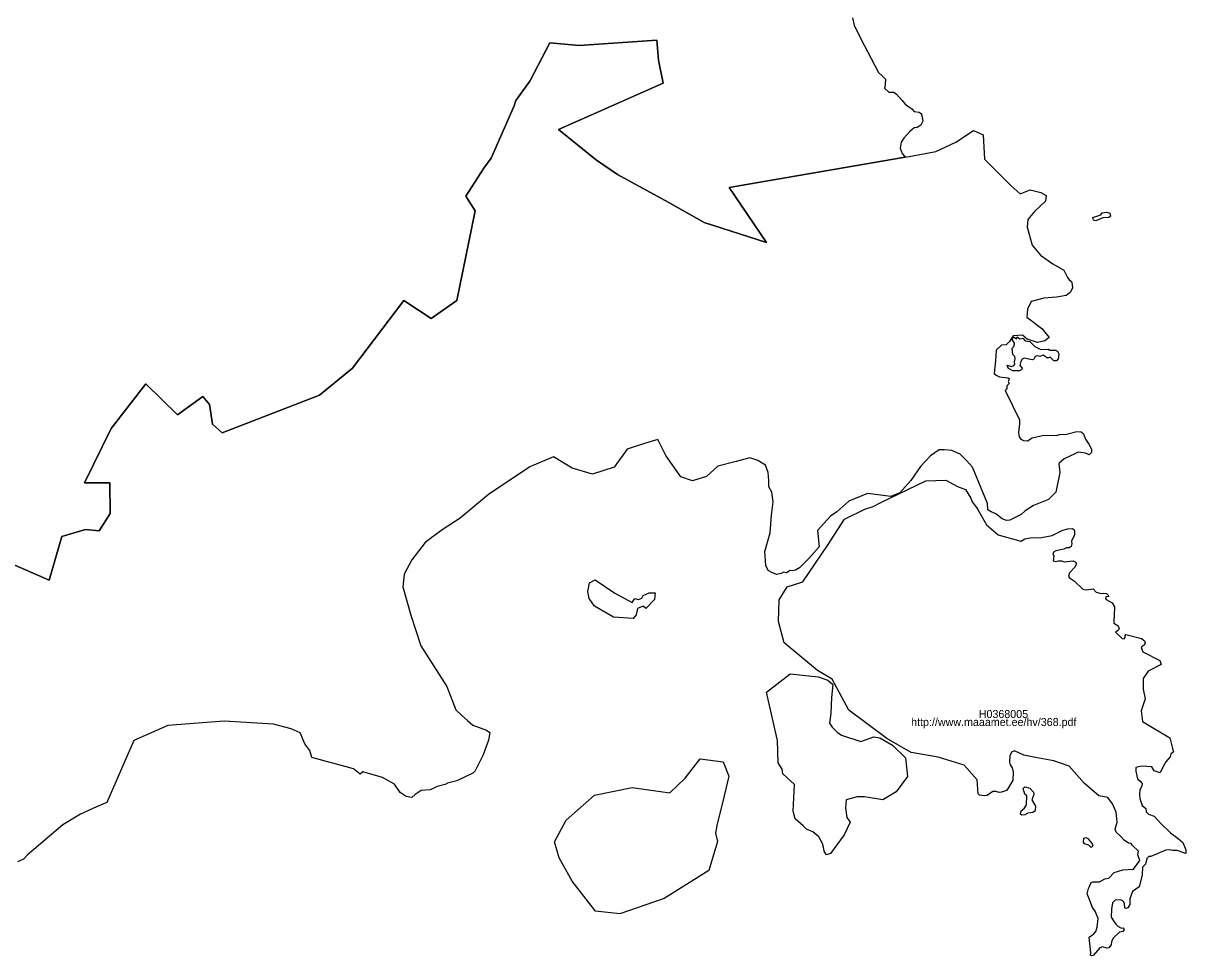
# Model space of a CAD drawing. Extents: x 369010 to 739155, y 6377141 to 6634081.
# Drawn here: x 432069 to 435701, y 6515722 to 6518635 of the extents above; entities that cross this region are included whole.
import ezdxf

# ---------------------------------------------------------------- set-up
doc = ezdxf.new("R2010")
doc.units = 0
for name, color, linetype in [('H_LINK', 7, 'Continuous'), ('H_PIIR', 7, 'Continuous'), ('H_TUNNUS', 7, 'Continuous')]:
    doc.layers.add(name, color=color, linetype=linetype)

msp = doc.modelspace()

# ---------------------------------------------------------------- linework, layer by layer
at = {"layer": 'H_PIIR'}
for points in [[(434660.1, 6518652.0146), (434664.5801, 6518629.5846), (434687.0001, 6518584.7346), (434706.42, 6518547.3647), (434740.79, 6518481.5847), (434752.7399, 6518471.1146), (434763.2001, 6518460.6546), (434761.71, 6518442.7146), (434760.2099, 6518432.2446), (434773.6601, 6518420.2846), (434789.35, 6518420.2846), (434797.1799, 6518413.6347), (434815.29, 6518394.4047), (434823.93, 6518382.9847), (434838.6599, 6518372.4546), (434845.1101, 6518367.6546), (434852.91, 6518360.1246), (434868.51, 6518358.1747), (434875.48, 6518352.0446), (434879.0999, 6518329.4746), (434873.2499, 6518316.9346), (434862.3799, 6518309.6847), (434852.77, 6518308.2846), (434837.45, 6518296.3047), (434820.1699, 6518275.9546), (434811.5299, 6518263.6946), (434809.03, 6518244.7446), (434814.75, 6518228.9347), (434822.22, 6518219.9646), (434823.8759, 6518217.4807), (434818.28, 6518216.51), (434274.3, 6518122.15), (434390.87, 6517950.0801), (434196.5901, 6518012.52), (434084.19, 6518076.3599), (433925.9901, 6518162.3899), (433859.38, 6518208.19), (433741.4201, 6518303.94), (434068.05, 6518448.41), (434053.77, 6518519.84), (434048.06, 6518582.7), (433805.3299, 6518565.56), (433713.95, 6518574.13), (433651.12, 6518454.12), (433608.29, 6518394.12), (433602.58, 6518376.9799), (433531.1899, 6518214.11), (433508.3401, 6518182.6801), (433451.82, 6518095.3999), (433480.37, 6518049.68), (433423.26, 6517769.66), (433343.3001, 6517712.52), (433257.63, 6517769.66), (433097.72, 6517558.2199), (432993.95, 6517473.18), (432689.82, 6517356.03), (432660.27, 6517383.29), (432650.2801, 6517444.7301), (432630.29, 6517469.01), (432550.3299, 6517411.87), (432451.8101, 6517509.01), (432343.3201, 6517369.21), (432260.51, 6517199.2), (432339.04, 6517199.4601), (432340.4701, 6517103.7401), (432306.2, 6517049.4501), (432263.37, 6517053.73), (432189.12, 6517032.3), (432149.14, 6516895.15), (431967.8001, 6516974.8599)], [(431967.8001, 6516974.8599), (432149.14, 6516895.15), (432189.12, 6517032.3), (432263.37, 6517053.73), (432306.2, 6517049.4501), (432340.4701, 6517103.7401), (432339.04, 6517199.4601), (432260.51, 6517199.2), (432343.3201, 6517369.21), (432451.8101, 6517509.01), (432550.3299, 6517411.87), (432630.29, 6517469.01), (432650.2801, 6517444.7301), (432660.27, 6517383.29), (432689.82, 6517356.03), (432993.95, 6517473.18), (433097.72, 6517558.2199), (433257.63, 6517769.66), (433343.3001, 6517712.52), (433423.26, 6517769.66), (433480.37, 6518049.68), (433451.82, 6518095.3999), (433508.3401, 6518182.6801), (433531.1899, 6518214.11), (433602.58, 6518376.9799), (433608.29, 6518394.12), (433651.12, 6518454.12), (433713.95, 6518574.13), (433805.3299, 6518565.56), (434048.06, 6518582.7), (434053.77, 6518519.84), (434068.05, 6518448.41), (433741.4201, 6518303.94), (433859.38, 6518208.19), (433925.9901, 6518162.3899), (434084.19, 6518076.3599), (434196.5901, 6518012.52), (434390.87, 6517950.0801), (434274.3, 6518122.15), (434818.28, 6518216.51), (434823.8759, 6518217.4807), (434836.7915, 6518219.0082), (434920.4, 6518234.3541), (434982.3126, 6518263.9875), (435038.4044, 6518300.2355), (435067.7732, 6518287.0063), (435071.8742, 6518211.203), (435155.2182, 6518127.8591), (435183.9255, 6518102.5913), (435214.4849, 6518115.2913), (435247.8225, 6518106.1632), (435265.285, 6518097.4319), (435262.5069, 6518079.1756), (435228.3756, 6518047.0287), (435207.3412, 6518022.8193), (435205.7537, 6517998.6099), (435221.6287, 6517942.2535), (435247.4256, 6517910.9003), (435285.9226, 6517883.9127), (435320.0539, 6517863.6721), (435331.4163, 6517841.3816), (435336.7299, 6517833.9601), (435343.9194, 6517828.747), (435346.2345, 6517818.8251), (435346.8959, 6517807.5803), (435339.6199, 6517794.3511), (435327.7136, 6517784.7599), (435296.9557, 6517779.1375), (435257.5989, 6517776.161), (435217.9113, 6517765.9083), (435206.3358, 6517741.7651), (435205.0128, 6517717.2911), (435251.6457, 6517681.5722), (435274.1354, 6517654.1217), (435261.2369, 6517643.2076), (435237.7551, 6517637.9159), (435205.3436, 6517648.4993), (435191.1222, 6517660.7363), (435161.6872, 6517659.0826), (435150.4424, 6517640.8373), (435139.7037, 6517630.8062), (435125.7816, 6517629.4936), (435108.8936, 6517613.7185), (435106.87, 6517580.68), (435102.73, 6517541.0146), (435109.13, 6517535.4447), (435119.1701, 6517530.7047), (435145.36, 6517527.3647), (435150.65, 6517524.2946), (435146.05, 6517516.2146), (435149.1199, 6517509.8046), (435141.87, 6517502.5547), (435141.5899, 6517493.9147), (435136.86, 6517487.7846), (435181.86, 6517396.0946), (435181.86, 6517382.7246), (435179.0699, 6517367.3947), (435178.5199, 6517355.6846), (435180.47, 6517342.8646), (435186.32, 6517336.4547), (435193.71, 6517331.4546), (435206.2499, 6517331.1747), (435221.01, 6517339.8147), (435257.5199, 6517348.4447), (435295.8301, 6517347.3247), (435307.8199, 6517350.9446), (435328.44, 6517351.2247), (435360.76, 6517360.1446), (435373.85, 6517359.0346), (435381.38, 6517352.6246), (435387.5101, 6517336.1746), (435398.1, 6517320.8547), (435406.73, 6517304.4046), (435407.0099, 6517294.0947), (435399.77, 6517286.8546), (435387.79, 6517292.7046), (435365.0346, 6517295.033), (435354.7445, 6517290.1781), (435321.07, 6517274.29), (435304.0995, 6517259.8366), (435307.2745, 6517232.3199), (435295.03, 6517169.89), (435272.52, 6517147.82), (435225.2707, 6517128.9103), (435199.26, 6517112.06), (435186.4401, 6517100.9101), (435168.0501, 6517090.88), (435150.92, 6517083.0801), (435140.61, 6517081.9701), (435127.23, 6517087.5401), (435107.73, 6517102.5901), (435092.68, 6517109.0001), (435082.93, 6517115.69), (435081.5301, 6517135.4701), (435034.434, 6517248.3796), (435016.11, 6517269.22), (434995.9187, 6517289.1806), (434969.94, 6517300.18), (434946.15, 6517302.16), (434930.5071, 6517302.17), (434904.0487, 6517284.1783), (434872.2986, 6517250.3116), (434841.6069, 6517206.9198), (434807.7402, 6517168.8197), (434779.1651, 6517157.178), (434707.1983, 6517166.7031), (434647.9315, 6517142.3614), (434611.2013, 6517108.6284), (434590.7628, 6517095.8242), (434550.0024, 6517050.6786), (434555.2941, 6516999.8785), (434523.544, 6516962.8368), (434494.5382, 6516934.4594), (434481.3681, 6516927.2093), (434473.4683, 6516924.5794), (434464.2583, 6516925.2394), (434458.9883, 6516921.9393), (434453.0582, 6516917.9893), (434444.5081, 6516920.6194), (434436.6082, 6516916.6693), (434422.7782, 6516912.7193), (434407.6383, 6516919.3094), (434396.4482, 6516925.2394), (434388.5481, 6516941.7093), (434385.9604, 6516985.0618), (434402.8938, 6517043.2703), (434407.1271, 6517098.3037), (434412, 6517140), (434408.01, 6517170.1747), (434398.79, 6517186.6446), (434398.13, 6517206.4147), (434396.1599, 6517232.1046), (434388, 6517255), (434364.2976, 6517269.3616), (434338.8976, 6517277.8283), (434296.5641, 6517266.1866), (434239.414, 6517251.3699), (434203.4306, 6517219.6198), (434160.0389, 6517205.8615), (434122.9971, 6517218.5615), (434076.4304, 6517285.2366), (434051.0303, 6517334.9784), (434009.7552, 6517322.2784), (433955.7801, 6517304.2867), (433915.5634, 6517248.1949), (433847.8299, 6517227.0282), (433784.3298, 6517245.0199), (433725.063, 6517281.0033), (433652.0379, 6517249.2532), (433522.9209, 6517163.5281), (433434.0208, 6517089.4446), (433377.929, 6517052.4028), (433325.0064, 6517013.2475), (433282.6788, 6516959.2693), (433258.3702, 6516914.3105), (433255.1621, 6516874.6025), (433279.5038, 6516785.9669), (433310.4601, 6516689.9229), (433392.2165, 6516563.7164), (433420.2293, 6516489.9637), (433438.9312, 6516472.6725), (433456.7419, 6516457.4199), (433473.0138, 6516442.7355), (433516.2733, 6516427.2573), (433526.9889, 6516419.3198), (433522.2264, 6516395.1104), (433505.9201, 6516349.6947), (433481.0899, 6516299.9947), (433473.25, 6516292.1446), (433423.8012, 6516268.1101), (433393.8312, 6516261.06), (433387.2713, 6516256.6701), (433361.9753, 6516250.388), (433351.5153, 6516245.148), (433340.0604, 6516240.3288), (433312.2249, 6516238.4615), (433293.5499, 6516226.1047), (433283.0999, 6516216.9447), (433264.8001, 6516219.5646), (433246.8917, 6516232.358), (433228.6016, 6516258.5181), (433191.0997, 6516278.7993), (433130.1899, 6516296.7247), (433121.0399, 6516288.8746), (433100.13, 6516305.8847), (432970.75, 6516341.1946), (432964.2201, 6516363.4247), (432948.5299, 6516384.3547), (432934.1601, 6516418.3547), (432905.41, 6516431.4346), (432850.3157, 6516445.787), (432696.3279, 6516455.312), (432520.115, 6516441.0245), (432414.0351, 6516394.9869), (432329.6146, 6516201.3115), (432297.8646, 6516187.024), (432247.5936, 6516164.7989), (432192.5602, 6516130.9322), (432081.0835, 6516036.6954), (432069.3234, 6516023.6155), (432051.0235, 6516015.7655)]]:
    msp.add_lwpolyline(points, dxfattribs=at)
for points in [[(435442.0215, 6518027.7548), (435420.5061, 6518018.6522), (435413.2238, 6518019.9761), (435410.4103, 6518028.0859), (435435.5669, 6518036.6921), (435440.0354, 6518042.8156), (435454.4344, 6518045.4638), (435464.0336, 6518042.3192), (435465.6886, 6518033.051), (435461.2199, 6518028.4168)], [(435173.9051, 6517656.0329), (435182.3457, 6517649.9093), (435192.1105, 6517652.0609), (435199.0616, 6517643.1235), (435214.1226, 6517641.1376), (435229.1834, 6517625.5802), (435248.0509, 6517616.643), (435271.5523, 6517617.4705), (435276.021, 6517614.1603), (435294.723, 6517613.8294), (435301.5087, 6517609.6918), (435304.4876, 6517601.0856), (435302.3362, 6517587.1832), (435297.04, 6517581.0595), (435288.5993, 6517581.0595), (435277.0139, 6517592.4794), (435269.0698, 6517589.0038), (435255.9951, 6517598.2719), (435245.2372, 6517593.8034), (435236.7965, 6517596.6169), (435230.673, 6517594.631), (435226.2043, 6517586.0247), (435221.2392, 6517583.7077), (435196.0826, 6517588.8382), (435190.4555, 6517585.6936), (435185.3248, 6517579.0735), (435182.3457, 6517565.6677), (435190.4555, 6517557.889), (435189.2969, 6517553.4203), (435182.0148, 6517549.1173), (435160.3336, 6517549.7794), (435146.4314, 6517557.889), (435143.6178, 6517567.6537), (435156.1961, 6517563.3506), (435163.6439, 6517565.9986), (435166.9539, 6517570.6328), (435165.6298, 6517577.9149), (435168.6089, 6517587.1832), (435167.2848, 6517594.631), (435160.8302, 6517600.7545), (435159.1752, 6517619.953), (435164.9678, 6517626.9042), (435166.4573, 6517636.1723), (435160.0027, 6517646.7647), (435161.1612, 6517652.8884), (435164.9678, 6517654.8743), (435172.581, 6517649.5782)], [(435108.01, 6516235.6246), (435098.5401, 6516235.6246), (435080.15, 6516223.0845), (435071.51, 6516221.1346), (435056.74, 6516223.6445), (435052.2799, 6516228.3845), (435049.0332, 6516272.04), (435008.9297, 6516317.2456), (434927.5702, 6516342.381), (434842.8801, 6516357.4246), (434767.497, 6516401.2509), (434648.8311, 6516488.8943), (434596.4435, 6516585.732), (434550.4059, 6516612.7196), (434446.0276, 6516699.5692), (434428.1682, 6516766.3767), (434430.1525, 6516834.507), (434455.1557, 6516874.6576), (434504.3683, 6516890.5326), (434582.156, 6517003.2454), (434634.9964, 6517086.327), (434698.4364, 6517117.397), (434724.151, 6517125.5421), (434748.4396, 6517138.5277), (434888.5441, 6517205.5859), (434951.3828, 6517207.5702), (434987.78, 6517188.46), (435012.8985, 6517179.1275), (435029.7345, 6517151.3233), (435033.6345, 6517140.4533), (435047.2944, 6517122.9034), (435052.5846, 6517113.7034), (435078.383, 6517068.0023), (435115.4247, 6517036.9137), (435186.32, 6517017.6546), (435198.58, 6517024.8947), (435215.0201, 6517027.9646), (435250.6899, 6517028.2447), (435283.43, 6517035.4846), (435317.1401, 6517051.3647), (435332.7501, 6517055.8247), (435347.24, 6517056.3847), (435352.2499, 6517052.4847), (435353.9299, 6517048.0246), (435353.3699, 6517036.8747), (435343.6201, 6517017.3647), (435345.01, 6517009.0046), (435343.34, 6517000.3646), (435337.2099, 6516996.1846), (435328.29, 6516996.1846), (435319.9299, 6516992.5647), (435294.85, 6516987.5446), (435287.89, 6516983.0846), (435285.9401, 6516976.1246), (435288.7199, 6516971.1047), (435287.33, 6516956.0547), (435292.62, 6516953.5446), (435303.49, 6516956.0547), (435312.69, 6516955.4947), (435321.6099, 6516952.4446), (435348.9101, 6516956.0647), (435357.83, 6516951.3246), (435358.94, 6516944.6347), (435353.65, 6516935.4447), (435338.05, 6516918.7147), (435334.7, 6516908.4046), (435337.7699, 6516903.1147), (435353.09, 6516891.9647), (435379.8399, 6516866.8846), (435389.8701, 6516865.2146), (435411.6099, 6516868.8346), (435421.64, 6516857.9647), (435437.1001, 6516853.5047), (435442.9501, 6516854.3446), (435453.8201, 6516854.0647), (435458.84, 6516849.0446), (435460.51, 6516844.5846), (435451.87, 6516843.7546), (435450.76, 6516838.1746), (435452.1501, 6516834.5546), (435471.38, 6516825.0847), (435478.2, 6516811.6946), (435478.76, 6516802.7746), (435477.3699, 6516793.0246), (435476.2499, 6516761.2546), (435489.6301, 6516752.8947), (435493.25, 6516743.9746), (435489.6301, 6516738.1247), (435482.1101, 6516732.5546), (435502.8601, 6516713.0446), (435508.43, 6516712.4846), (435512.0599, 6516715.8246), (435512.34, 6516722.5147), (435514.2899, 6516725.8647), (435563.3299, 6516713.0446), (435572.24, 6516705.5146), (435574.06, 6516699.6546), (435571.5501, 6516692.6946), (435564.86, 6516689.3446), (435561.8001, 6516684.8847), (435566.54, 6516671.5146), (435620.0401, 6516644.2046), (435623.9399, 6516631.6646), (435583.29, 6516611.6), (435568.5246, 6516588.444), (435567.8632, 6516554.7096), (435574.4777, 6516524.2824), (435561.91, 6516487.2407), (435565.8788, 6516453.5062), (435651.8685, 6516403.2353), (435659.8499, 6516369.2299), (435663.1133, 6516359.579), (435654.83, 6516351.67), (435652.3199, 6516343.03), (435639.2298, 6516328.2599), (435629.47, 6516311.5399), (435621.4414, 6516293.433), (435602.7715, 6516299.8429), (435595.2415, 6516312.1029), (435563.4815, 6516314.3329), (435545.3735, 6516309.9695), (435544.7223, 6516298.5357), (435550.2659, 6516274.594), (435558.9446, 6516267.662), (435564.5559, 6516259.6986), (435564.2859, 6516253.0087), (435557.806, 6516238.9228), (435556.4159, 6516225.5428), (435557.5259, 6516213.5627), (435564.4959, 6516191.2627), (435576.2909, 6516181.7284), (435577.681, 6516171.6983), (435585.0611, 6516164.4484), (435602.061, 6516158.5884), (435623.4258, 6516134.6827), (435653.8529, 6516105.5785), (435677.7201, 6516088.5046), (435691.65, 6516075.4046), (435701.13, 6516052.8246), (435701.13, 6516041.6847), (435674.38, 6516050.8747), (435659.3301, 6516050.3247), (435649.02, 6516053.3846), (435638.4299, 6516051.4347), (435591.7601, 6516031.6547), (435585.3499, 6516031.9246), (435579.22, 6516026.0747), (435575.32, 6516007.6846), (435566.4001, 6515998.7647), (435565.01, 6515973.6846), (435555.2954, 6515937.5677), (435534.4055, 6515923.0777), (435525.9099, 6515899.338), (435526.7398, 6515882.618), (435520.3299, 6515871.4681), (435515.32, 6515869.5181), (435510.8599, 6515870.628), (435510.0198, 6515884.848), (435505.8399, 6515892.0881), (435498.8799, 6515895.438), (435481.221, 6515896.5468), (435472.581, 6515887.0669), (435468.961, 6515867.2868), (435468.2711, 6515843.0268), (435475.5501, 6515831.2646), (435482.24, 6515820.6746), (435489.21, 6515814.2647), (435498.6801, 6515808.9747), (435506.4638, 6515807.9974), (435508.99, 6515803.9447), (435504.5399, 6515798.0947), (435493.95, 6515795.3147), (435474.86, 6515777.4646), (435469.01, 6515766.8747), (435467.9, 6515756.0047), (435460.37, 6515746.8047), (435454.8, 6515745.6947), (435441.43, 6515749.8746), (435433.0701, 6515746.2547), (435411.6099, 6515722.8446), (435407.1501, 6515722.0047), (435403.5299, 6515724.2347), (435404.37, 6515731.2047), (435399.21, 6515779.6947), (435414.25, 6515790.2846), (435420.3801, 6515798.0847), (435424.8399, 6515811.7446), (435427.07, 6515837.9347), (435417.68, 6515861.09), (435410.104, 6515872.4843), (435401.1753, 6515894.5728), (435392.5763, 6515915.7395), (435397.67, 6515932.1346), (435400.46, 6515938.5446), (435405.47, 6515950.8046), (435410.4899, 6515953.3147), (435431.52, 6515952.7647), (435447.9599, 6515961.9647), (435460.7801, 6515964.4646), (435476.9401, 6515981.7446), (435504.1101, 6515990.1147), (435537.83, 6515992.3446), (435558.1699, 6516019.9346), (435551.1999, 6516037.4947), (435553.7101, 6516048.3646), (435534.2, 6516067.0347), (435530.5801, 6516072.6046), (435522.22, 6516074.0047), (435508.29, 6516082.9146), (435498.67, 6516094.9046), (435483.3501, 6516108.0047), (435480.2799, 6516117.2047), (435486.41, 6516138.9446), (435483.3501, 6516170.4346), (435471.9515, 6516196.8599), (435457.3994, 6516216.7037), (435429.6181, 6516221.9954), (435383.9774, 6516261.6829), (435336.87, 6516314.53), (435288.7272, 6516331.1362), (435231.1802, 6516341.7196), (435195.4614, 6516348.9956), (435166.0444, 6516362.395), (435156.5743, 6516357.9351), (435151.8344, 6516346.235), (435150.4444, 6516327.285), (435152.3944, 6516318.085), (435159.0744, 6516308.8951), (435161.7269, 6516295.4174), (435161.0655, 6516270.9434), (435146.5133, 6516245.1464), (435140.5602, 6516237.8704), (435125.29, 6516232.8345), (435117.76, 6516232.0046)], [(434043.4963, 6516855.6517), (434041.0136, 6516835.1292), (434013.8497, 6516806.6103), (434005.74, 6516814.72), (433988.031, 6516806.6103), (433983.8935, 6516787.5772), (433974.043, 6516775.615), (433912.5273, 6516780.2453), (433853.6574, 6516813.9797), (433837.1209, 6516837.7923), (433833.1521, 6516859.6204), (433838.4438, 6516886.7403), (433855.6463, 6516896.1729), (433917.1575, 6516854.3287), (433971.684, 6516825.8648), (433979.7937, 6516838.1122), (433990.7169, 6516835.2985), (434001.6402, 6516839.4361), (434005.6123, 6516847.5459), (434024.6288, 6516855.6517)], [(434784.7611, 6516379.7645), (434825.2424, 6516340.0769), (434831.5924, 6516282.1331), (434796.6673, 6516234.508), (434754.5985, 6516209.1079), (434697.4484, 6516218.6329), (434674.4296, 6516218.6329), (434639.8421, 6516208.6693), (434638.1871, 6516183.6783), (434642.3248, 6516153.8875), (434652.2549, 6516139.8197), (434633.9483, 6516099.5702), (434591.4086, 6516041.757), (434578.1682, 6516037.6193), (434571.548, 6516048.3771), (434569.0654, 6516060.7899), (434565.7554, 6516073.2028), (434554.17, 6516093.0632), (434535.9646, 6516109.6136), (434516.1042, 6516117.8887), (434505.3464, 6516127.819), (434480.7542, 6516149.5766), (434473.982, 6516173.9974), (434478.373, 6516257.5268), (434442.075, 6516290.8027), (434439.9584, 6516304.5611), (434427.2583, 6516324.6694), (434425.0262, 6516394.482), (434391.1595, 6516545.824), (434465.243, 6516602.9741), (434552.0265, 6516593.4491), (434583.1151, 6516583.0641), (434598.3287, 6516569.8349), (434594.6906, 6516528.4937), (434591.7141, 6516480.2072), (434588.076, 6516449.1186), (434596.3443, 6516436.2201), (434611.8886, 6516421.0065), (434625.4485, 6516411.4154), (434685.5421, 6516390.877), (434726.8172, 6516405.9583), (434745.0735, 6516402.7833)], [(434210.4487, 6515988.7647), (434071.8068, 6515900.9228), (433933.1648, 6515853.2977), (433856.9647, 6515861.7644), (433783.9395, 6515954.898), (433743.7228, 6516027.9231), (433728.9061, 6516077.6649), (433764.8895, 6516145.3983), (433853.7897, 6516223.7152), (433971.2649, 6516248.0569), (434088.7401, 6516231.1235), (434137.4236, 6516276.6319), (434183.9903, 6516336.957), (434255.9571, 6516327.432), (434272.8905, 6516282.9819), (434253.8405, 6516199.3734), (434236.9071, 6516133.7566), (434231.6154, 6516105.1816), (434237.9654, 6516078.7232)], [(435197.9031, 6516162.0284), (435188.966, 6516161.0352), (435184.8282, 6516164.0143), (435186.8144, 6516174.9376), (435196.579, 6516181.5577), (435204.0268, 6516193.9705), (435204.8543, 6516222.1063), (435198.7306, 6516227.0713), (435193.4344, 6516244.2838), (435198.7306, 6516249.58), (435213.7915, 6516245.4424), (435225.5423, 6516232.8641), (435226.3698, 6516225.9129), (435220.2461, 6516209.528), (435231.6659, 6516189.1709), (435230.8384, 6516174.6067), (435223.0597, 6516169.3105), (435207.1714, 6516167.9864)], [(435411.2378, 6516065.043), (435405.7762, 6516059.7468), (435398.494, 6516067.8565), (435385.0882, 6516071.9941), (435381.4471, 6516076.4627), (435383.1021, 6516089.372), (435388.7292, 6516091.0272), (435395.1838, 6516088.2135), (435408.7553, 6516071.4976)], [(435506.4638, 6515807.9974), (435506.2099, 6515808.4047), (435507.6, 6515807.8547)]]:
    msp.add_lwpolyline(points, close=True, dxfattribs=at)

# ---------------------------------------------------------------- texts
at = {"layer": 'H_LINK'}
msp.add_text('http://www.maaamet.ee/hv/368.pdf', height=25, dxfattribs=at).set_placement((434843.0369, 6516439.7874))
at = {"layer": 'H_TUNNUS'}
msp.add_text('H0368005', height=25, dxfattribs=at).set_placement((435054.2658, 6516464.7874))

doc.saveas('drawing.dxf')
